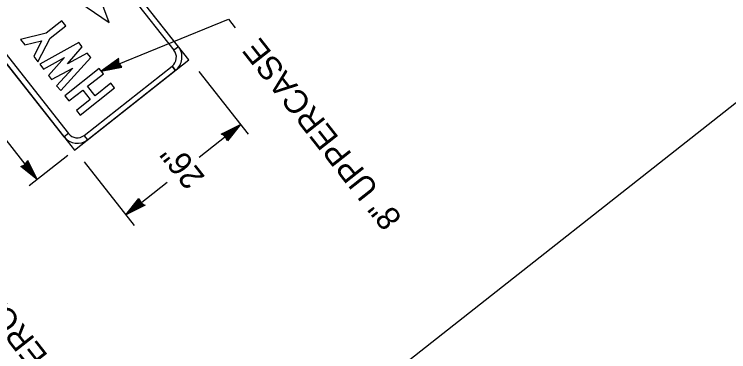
# Model space of a CAD drawing. Extents: x 672239 to 673995, y 1673540 to 1675195.
# Drawn here: x 672425.9 to 672553.6, y 1674877.9 to 1674938.1 of the extents above; entities that cross this region are included whole.
import ezdxf

# ---------------------------------------------------------------- set-up
doc = ezdxf.new("R2010")
doc.units = 0
doc.layers.add('C-ALGN-SYMB', color=7, linetype='Continuous')
doc.layers.add('C-ANNO-SYMB', color=7, linetype='Continuous')

msp = doc.modelspace()

# ---------------------------------------------------------------- linework, layer by layer
at = {"layer": 'C-ALGN-SYMB'}
for p, q in [((672675.29, 1675017.25), (672379.17, 1674783.8)), ((672430.02, 1674908.6), (672410.26, 1674933.67)), ((672444.61, 1674930.24), (672441.49, 1674927.97)), ((672444.43, 1674929.93), (672441.85, 1674928.07)), ((672444.48, 1674930.09), (672442.01, 1674928.17)), ((672444.44, 1674929.79), (672442.4, 1674928.38)), ((672444.44, 1674929.79), (672442.54, 1674928.39)), ((672444.41, 1674929.6), (672443.04, 1674928.61)), ((672444.37, 1674929.44), (672443.46, 1674928.83)), ((672444.29, 1674929.17), (672444.46, 1674929.48)), ((672444.49, 1674928.97), (672444.37, 1674929.44)), ((672444.64, 1674928.96), (672444.41, 1674929.6)), ((672444.51, 1674929.87), (672444.43, 1674929.93)), ((672444.69, 1674929.04), (672444.44, 1674929.79)), ((672444.74, 1674928.86), (672444.44, 1674929.79)), ((672444.46, 1674929.48), (672444.53, 1674929.02)), ((672444.5, 1674929.72), (672444.48, 1674930.09)), ((672444.66, 1674929.37), (672444.5, 1674929.72)), ((672444.56, 1674930.1), (672444.51, 1674929.87)), ((672444.67, 1674929.28), (672444.56, 1674930.1)), ((672445.15, 1674928.67), (672444.66, 1674929.37)), ((672441.49, 1674927.97), (672445.15, 1674928.67)), ((672441.8, 1674928.05), (672445.01, 1674928.72)), ((672442.01, 1674928.17), (672441.8, 1674928.05)), ((672441.85, 1674928.07), (672441.97, 1674928.24)), ((672441.97, 1674928.24), (672442.72, 1674928.75)), ((672442.21, 1674928.23), (672444.86, 1674928.8)), ((672442.72, 1674928.75), (672442.21, 1674928.23)), ((672442.4, 1674928.38), (672444.64, 1674928.96)), ((672442.54, 1674928.39), (672444.74, 1674928.86)), ((672442.94, 1674928.59), (672443.32, 1674928.88)), ((672443.41, 1674928.75), (672442.94, 1674928.59)), ((672443.04, 1674928.61), (672444.49, 1674928.97)), ((672443.62, 1674928.93), (672443.41, 1674928.75)), ((672443.46, 1674928.83), (672444.36, 1674929)), ((672444.53, 1674929.02), (672443.62, 1674928.93)), ((672444.36, 1674929.32), (672443.88, 1674928.99)), ((672443.88, 1674928.99), (672444.31, 1674929.07)), ((672444.31, 1674929.07), (672444.29, 1674929.17)), ((672444.36, 1674929), (672444.36, 1674929.32)), ((672445.01, 1674928.72), (672444.67, 1674929.28)), ((672444.86, 1674928.8), (672444.69, 1674929.04)), ((672458.89, 1674927.91), (672467.72, 1674916.71)), ((672458.96, 1674912.62), (672466.35, 1674918.45)), ((672462.89, 1674916.74), (672466.35, 1674918.45)), ((672463.08, 1674916.8), (672465.93, 1674918.09)), ((672463.25, 1674916.76), (672466.09, 1674918.18)), ((672466.35, 1674918.45), (672464.03, 1674915.54)), ((672466.13, 1674918.21), (672464.05, 1674915.69)), ((672465.78, 1674917.93), (672464.05, 1674915.85)), ((672465.89, 1674918.15), (672465.09, 1674917.72)), ((672465.09, 1674917.72), (672465.78, 1674917.93)), ((672466.09, 1674918.18), (672465.89, 1674918.15)), ((672465.93, 1674918.09), (672466.13, 1674918.21)), ((672463.71, 1674916.25), (672463.04, 1674916.72)), ((672463.04, 1674916.72), (672463.26, 1674916.66)), ((672463.4, 1674916.61), (672463.08, 1674916.8)), ((672463.26, 1674916.66), (672463.25, 1674916.76)), ((672463.37, 1674916.68), (672465.56, 1674917.84)), ((672463.37, 1674916.68), (672465.49, 1674917.71)), ((672463.91, 1674916.11), (672463.37, 1674916.68)), ((672464.05, 1674915.99), (672463.37, 1674916.68)), ((672463.64, 1674916.3), (672463.4, 1674916.61)), ((672463.55, 1674916.63), (672465.06, 1674917.37)), ((672464.01, 1674916.12), (672463.55, 1674916.63)), ((672463.71, 1674916.59), (672464.67, 1674917.1)), ((672464.06, 1674916.26), (672463.71, 1674916.59)), ((672463.82, 1674916.54), (672464.34, 1674916.81)), ((672465.56, 1674917.84), (672464.01, 1674916.12)), ((672464.01, 1674916.25), (672464.51, 1674917.01)), ((672465.49, 1674917.71), (672464.05, 1674915.99)), ((672465.06, 1674917.37), (672464.06, 1674916.26)), ((672464.34, 1674916.81), (672464.07, 1674916.47)), ((672464.67, 1674917.1), (672464.1, 1674916.39)), ((672464.51, 1674917.01), (672464.77, 1674917.11)), ((672465.13, 1674917.46), (672464.69, 1674917.25)), ((672464.77, 1674917.11), (672465.13, 1674917.46)), ((672463.99, 1674916.53), (672463.63, 1674916.52)), ((672463.63, 1674916.52), (672464.01, 1674916.25)), ((672464.03, 1674915.54), (672463.64, 1674916.3)), ((672464.05, 1674915.69), (672463.71, 1674916.25)), ((672464.1, 1674916.39), (672463.82, 1674916.54)), ((672464.05, 1674915.85), (672463.91, 1674916.11)), ((672464.07, 1674916.47), (672463.99, 1674916.53)), ((672435.48, 1674912.9), (672428.58, 1674907.46)), ((672427.56, 1674910.9), (672428.26, 1674911.58)), ((672427.69, 1674911.04), (672428.26, 1674911.58)), ((672427.83, 1674911.24), (672428.3, 1674911.91)), ((672427.87, 1674911.31), (672428.18, 1674911.55)), ((672428.18, 1674911.55), (672428.37, 1674911.87)), ((672428.3, 1674911.91), (672428.24, 1674911.69)), ((672428.24, 1674911.69), (672428.33, 1674911.7)), ((672428.26, 1674911.58), (672429.29, 1674909.46)), ((672428.26, 1674911.58), (672429.41, 1674909.39)), ((672428.32, 1674912.06), (672430.02, 1674908.6)), ((672428.33, 1674911.7), (672429.76, 1674908.86)), ((672428.37, 1674911.87), (672429.66, 1674909.02)), ((672438.43, 1674911.78), (672447.38, 1674900.42)), ((672427.11, 1674910.92), (672427.87, 1674911.31)), ((672430.02, 1674908.6), (672427.11, 1674910.92)), ((672427.26, 1674910.9), (672427.83, 1674911.24)), ((672429.79, 1674908.82), (672427.26, 1674910.9)), ((672427.43, 1674910.9), (672427.69, 1674911.04)), ((672429.51, 1674909.17), (672427.43, 1674910.9)), ((672429.29, 1674909.46), (672427.56, 1674910.9)), ((672427.7, 1674910.94), (672428.2, 1674911.4)), ((672429.41, 1674909.39), (672427.7, 1674910.94)), ((672428.1, 1674911.32), (672427.83, 1674910.95)), ((672427.83, 1674910.95), (672428.59, 1674910.44)), ((672427.84, 1674910.89), (672428.16, 1674911.24)), ((672428.95, 1674909.89), (672427.84, 1674910.89)), ((672427.97, 1674910.85), (672428.11, 1674911.13)), ((672428.68, 1674910.28), (672427.97, 1674910.85)), ((672428.05, 1674910.88), (672428.11, 1674910.96)), ((672428.38, 1674910.62), (672428.05, 1674910.88)), ((672428.11, 1674910.96), (672428.1, 1674911.32)), ((672428.11, 1674911.13), (672428.38, 1674910.62)), ((672428.16, 1674911.24), (672428.68, 1674910.28)), ((672428.2, 1674911.4), (672428.95, 1674909.89)), ((672428.59, 1674910.44), (672428.69, 1674910.19)), ((672428.69, 1674910.19), (672429.03, 1674909.82)), ((672429.03, 1674909.82), (672428.83, 1674910.26)), ((672429.73, 1674909.07), (672429.3, 1674909.87)), ((672429.3, 1674909.87), (672429.51, 1674909.17)), ((672429.66, 1674909.02), (672429.79, 1674908.82)), ((672429.76, 1674908.86), (672429.73, 1674909.07)), ((672445.89, 1674902.31), (672453.28, 1674908.14)), ((672445.89, 1674902.31), (672448.21, 1674905.22)), ((672448.21, 1674905.22), (672448.6, 1674904.46)), ((672449.35, 1674904.02), (672445.89, 1674902.31)), ((672446.11, 1674902.55), (672448.19, 1674905.07)), ((672448.99, 1674904), (672446.15, 1674902.58)), ((672449.16, 1674903.96), (672446.31, 1674902.67)), ((672446.46, 1674902.82), (672448.19, 1674904.9)), ((672446.68, 1674902.92), (672448.23, 1674904.64)), ((672448.87, 1674904.07), (672446.68, 1674902.92)), ((672446.75, 1674903.05), (672448.19, 1674904.77)), ((672448.87, 1674904.07), (672446.75, 1674903.05)), ((672447.18, 1674903.39), (672448.18, 1674904.5)), ((672448.69, 1674904.13), (672447.18, 1674903.39)), ((672447.57, 1674903.66), (672448.14, 1674904.37)), ((672448.53, 1674904.17), (672447.57, 1674903.66)), ((672448.23, 1674904.51), (672447.73, 1674903.75)), ((672447.9, 1674903.95), (672448.17, 1674904.29)), ((672448.42, 1674904.22), (672447.9, 1674903.95)), ((672448.14, 1674904.37), (672448.42, 1674904.22)), ((672448.17, 1674904.29), (672448.25, 1674904.23)), ((672448.18, 1674904.5), (672448.53, 1674904.17)), ((672448.19, 1674905.07), (672448.53, 1674904.51)), ((672448.19, 1674904.9), (672448.33, 1674904.64)), ((672448.19, 1674904.77), (672448.87, 1674904.07)), ((672448.23, 1674904.64), (672448.69, 1674904.13)), ((672448.61, 1674904.24), (672448.23, 1674904.51)), ((672448.25, 1674904.23), (672448.61, 1674904.24)), ((672448.33, 1674904.64), (672448.87, 1674904.07)), ((672448.53, 1674904.51), (672449.2, 1674904.03)), ((672448.6, 1674904.46), (672448.84, 1674904.15)), ((672448.84, 1674904.15), (672449.16, 1674903.96)), ((672449.2, 1674904.03), (672448.98, 1674904.1)), ((672448.98, 1674904.1), (672448.99, 1674904)), ((672446.31, 1674902.67), (672446.11, 1674902.55)), ((672446.15, 1674902.58), (672446.36, 1674902.61)), ((672446.36, 1674902.61), (672447.15, 1674903.04)), ((672447.15, 1674903.04), (672446.46, 1674902.82)), ((672447.47, 1674903.65), (672447.11, 1674903.3)), ((672447.11, 1674903.3), (672447.55, 1674903.51)), ((672447.73, 1674903.75), (672447.47, 1674903.65))]:
    msp.add_line(p, q, dxfattribs=at)
msp.add_lwpolyline([(672441.49, 1674927.97), (672464.2, 1674937.23), (672465.43, 1674935.67)], dxfattribs=at)
at = {"layer": 'C-ANNO-SYMB'}
for p, q in [((672457.11, 1674929.96), (672405.11, 1674995.92)), ((672455.26, 1674932.31), (672406.97, 1674993.57)), ((672406.18, 1674992.95), (672454.47, 1674931.69)), ((672384.69, 1674979.83), (672436.7, 1674913.86)), ((672387.33, 1674978.09), (672435.62, 1674916.83)), ((672434.84, 1674916.22), (672386.55, 1674977.47)), ((672442.91, 1674936.67), (672439.99, 1674944.4)), ((672436.07, 1674941.31), (672442.91, 1674936.67)), ((672442.91, 1674936.67), (672442.91, 1674936.67)), ((672442.91, 1674936.67), (672442.91, 1674936.67)), ((672442.95, 1674936.62), (672442.95, 1674936.62)), ((672442.95, 1674936.62), (672442.95, 1674936.62)), ((672455.26, 1674932.31), (672454.47, 1674931.69)), ((672455.26, 1674932.31), (672454.47, 1674931.69)), ((672454.47, 1674931.69), (672454.47, 1674931.69)), ((672454.47, 1674931.69), (672454.47, 1674931.69)), ((672436.7, 1674913.86), (672457.11, 1674929.96)), ((672457.11, 1674929.96), (672457.11, 1674929.96)), ((672457.11, 1674929.96), (672457.11, 1674929.96)), ((672438.43, 1674916.5), (672454.14, 1674928.88)), ((672454.76, 1674928.1), (672439.05, 1674915.72)), ((672454.14, 1674928.88), (672454.76, 1674928.1)), ((672454.76, 1674928.1), (672454.14, 1674928.88)), ((672435.62, 1674916.83), (672434.84, 1674916.22)), ((672435.62, 1674916.83), (672434.84, 1674916.22)), ((672439.05, 1674915.72), (672438.43, 1674916.5)), ((672438.43, 1674916.5), (672438.43, 1674916.5)), ((672438.43, 1674916.5), (672438.43, 1674916.5)), ((672439.05, 1674915.72), (672438.43, 1674916.5))]:
    msp.add_line(p, q, dxfattribs=at)
for points in [[(672427.8, 1674932.67), (672430.8, 1674933.37), (672429.43, 1674930.59), (672430.17, 1674929.65), (672432.33, 1674933.84), (672435.12, 1674936.04), (672434.42, 1674936.93), (672431.63, 1674934.73), (672427.04, 1674933.63)], [(672439.59, 1674930.38), (672438.94, 1674931.2), (672435.47, 1674929.29), (672438.06, 1674932.31), (672437.46, 1674933.08), (672430.51, 1674929.22), (672431.15, 1674928.31), (672434.89, 1674930.38), (672432.05, 1674927.17), (672432.6, 1674926.47), (672436.39, 1674928.47), (672433.49, 1674925.34), (672434.23, 1674924.5)], [(672443.86, 1674924.96), (672443.2, 1674925.8), (672440.37, 1674923.58), (672439.03, 1674925.27), (672441.86, 1674927.5), (672441.12, 1674928.44), (672434.96, 1674923.58), (672435.7, 1674922.64), (672438.17, 1674924.59), (672439.51, 1674922.89), (672437.03, 1674920.95), (672437.7, 1674920.1)]]:
    msp.add_lwpolyline(points, close=True, dxfattribs=at)
for centre, radius, start, end in [((672452.9, 1674930.45), 3, 308.2504, 38.2506), ((672452.9, 1674930.45), 2, 308.2504, 38.2506), ((672437.19, 1674918.07), 2, 218.2508, 308.2504), ((672437.19, 1674918.07), 3, 218.2508, 308.2504)]:
    msp.add_arc(centre, radius, start, end, dxfattribs=at)

# ---------------------------------------------------------------- texts
at = {"layer": 'C-ALGN-SYMB'}
for s, p in [('8" UPPERCASE', (672495.35, 1674901.73)), ('26"', (672460.14, 1674909.04)), ('8" UPPERCASE', (672443.38, 1674862.84))]:
    msp.add_text(s, height=4.2, rotation=128.2505, dxfattribs=at).set_placement(p)

doc.saveas('drawing.dxf')
